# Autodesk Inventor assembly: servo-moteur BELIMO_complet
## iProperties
Author: Administrateur
Shininess: 22.0
Length Units: 11269
Angle Units: 11283
Time Units: 11279
Mass Units: 11290
Length Display Precision: 3
Angle Display Precision: 2
Compacted: False
PropertySet Name: _Private Model Information
Created: 2001-04
Part Number: servo-moteur BELIMO_complet
Document SubType Name: Assemblage
Designer: Administrateur
Control State: 0
Master: False
Checked Out: False
PropertySet Name: Design Tracking Control
Density: 0.0
Volumn: 0.0
Area: 0.0
PropertySet Name: Model Information
